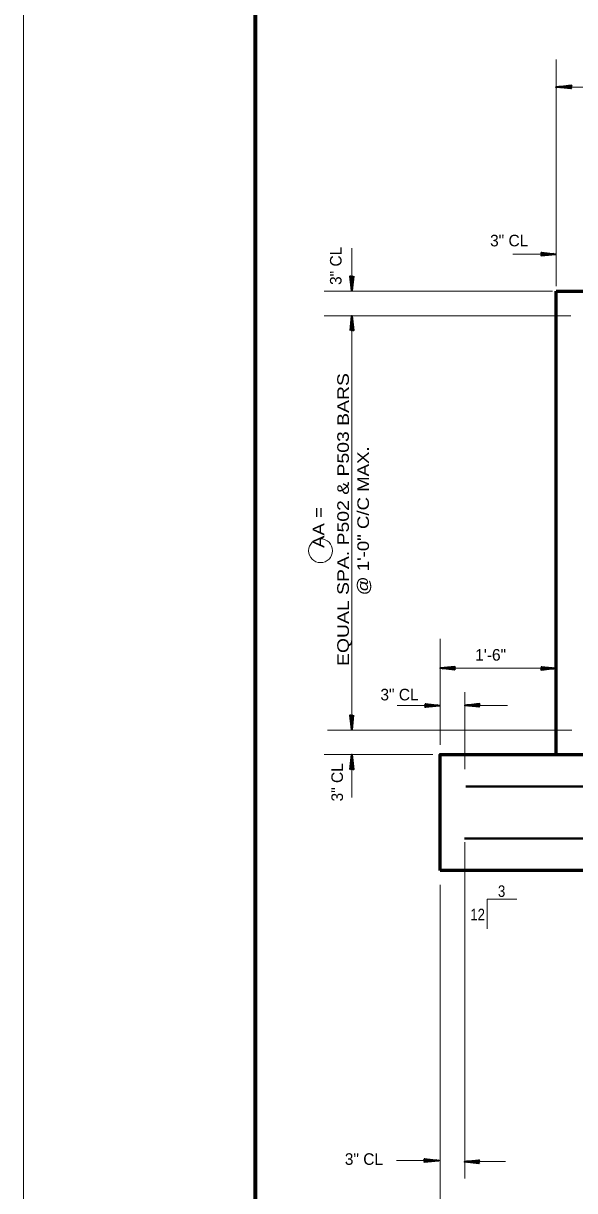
# Model space of a CAD drawing. Extents: x 6.34 to 9.53, y -1.46 to 0.53.
# Drawn here: x 6.336 to 6.732, y -1.036 to -0.197 of the extents above; entities that cross this region are included whole.
import ezdxf
from ezdxf.enums import TextEntityAlignment as Align

# ---------------------------------------------------------------- set-up
doc = ezdxf.new("R2010")
doc.units = 0
doc.header["$LTSCALE"] = 0.0033
doc.layers.add('1', color=7, linetype='Continuous', lineweight=40)

msp = doc.modelspace()

# ---------------------------------------------------------------- linework, layer by layer
at = {"layer": '1', "lineweight": 13}
for p, q in [((6.336, -1.46), (6.336, 0.52825)), ((6.718917, -0.386083), (6.718917, -0.222917)), ((6.572167, -0.3795), (6.572167, -0.358667)), ((6.687917, -0.362917), (6.70875, -0.362917)), ((6.716333, -0.389583), (6.55225, -0.389583)), ((6.729583, -0.40725), (6.552333, -0.40725)), ((6.572083, -0.704833), (6.572083, -0.408083)), ((6.635583, -0.715917), (6.635583, -0.639583)), ((6.6355, -0.660833), (6.718417, -0.660833)), ((6.65325, -0.733333), (6.65325, -0.678083)), ((6.60475, -0.6875), (6.625583, -0.6875)), ((6.66325, -0.6875), (6.684083, -0.6875)), ((6.730333, -0.70525), (6.55475, -0.70525)), ((6.630333, -0.722917), (6.55225, -0.722917)), ((6.572083, -0.753667), (6.572083, -0.732833)), ((6.65325, -0.78575), (6.65325, -1.027667)), ((6.635583, -0.8165), (6.635583, -1.076917)), ((6.669417, -0.826917), (6.69075, -0.826917)), ((6.669417, -0.826917), (6.669417, -0.84825)), ((6.60425, -1.014833), (6.625083, -1.014833)), ((6.66175, -1.015583), (6.682583, -1.015583))]:
    msp.add_line(p, q, dxfattribs=at)
at = {"layer": '1', "lineweight": 35}
for p, q in [((6.73, -0.242917), (6.719417, -0.242917)), ((6.72975, -0.24375), (6.721917, -0.24275)), ((6.72975, -0.24375), (6.721917, -0.242917)), ((6.72975, -0.243917), (6.721917, -0.243)), ((6.72975, -0.243917), (6.721917, -0.243)), ((6.72975, -0.243833), (6.721917, -0.243)), ((6.72975, -0.241833), (6.722417, -0.242667)), ((6.72975, -0.242), (6.722417, -0.24275)), ((6.72975, -0.242083), (6.722417, -0.242917)), ((6.729833, -0.24225), (6.7225, -0.243)), ((6.70825, -0.362917), (6.718833, -0.362917)), ((6.708417, -0.363583), (6.71575, -0.362833)), ((6.7085, -0.361917), (6.716333, -0.362833)), ((6.7085, -0.361917), (6.716333, -0.362833)), ((6.7085, -0.362), (6.716333, -0.362833)), ((6.7085, -0.362083), (6.716333, -0.362917)), ((6.7085, -0.362083), (6.716333, -0.363083)), ((6.7085, -0.36375), (6.715833, -0.362917)), ((6.7085, -0.363833), (6.715833, -0.363083)), ((6.7085, -0.364), (6.715833, -0.363167)), ((6.571083, -0.379167), (6.571917, -0.3865)), ((6.57125, -0.379167), (6.572, -0.3865)), ((6.571333, -0.379167), (6.572167, -0.3865)), ((6.5715, -0.379083), (6.57225, -0.386417)), ((6.573, -0.379167), (6.572, -0.387)), ((6.572167, -0.378917), (6.572167, -0.3895)), ((6.573, -0.379167), (6.572167, -0.387)), ((6.573167, -0.379167), (6.57225, -0.387)), ((6.573167, -0.379167), (6.57225, -0.387)), ((6.573083, -0.379167), (6.57225, -0.387)), ((6.571167, -0.417583), (6.572083, -0.40975)), ((6.571167, -0.417583), (6.572083, -0.40975)), ((6.57125, -0.417583), (6.572083, -0.40975)), ((6.571333, -0.417583), (6.572167, -0.40975)), ((6.571333, -0.417583), (6.572333, -0.40975)), ((6.572833, -0.417667), (6.572083, -0.410333)), ((6.572167, -0.417833), (6.572167, -0.40725)), ((6.573, -0.417583), (6.572167, -0.41025)), ((6.573083, -0.417583), (6.572333, -0.41025)), ((6.57325, -0.417583), (6.572417, -0.41025)), ((6.646167, -0.660833), (6.635583, -0.660833)), ((6.645917, -0.661667), (6.638083, -0.660667)), ((6.645917, -0.661667), (6.638083, -0.660833)), ((6.645917, -0.661833), (6.638083, -0.660917)), ((6.645917, -0.661833), (6.638083, -0.660917)), ((6.645917, -0.66175), (6.638083, -0.660917)), ((6.645917, -0.65975), (6.638583, -0.660583)), ((6.645917, -0.659917), (6.638583, -0.660667)), ((6.645917, -0.66), (6.638583, -0.660833)), ((6.646, -0.660167), (6.638667, -0.660917)), ((6.70825, -0.660833), (6.718833, -0.660833)), ((6.708417, -0.6615), (6.71575, -0.66075)), ((6.7085, -0.659833), (6.716333, -0.66075)), ((6.7085, -0.659833), (6.716333, -0.66075)), ((6.7085, -0.659917), (6.716333, -0.66075)), ((6.7085, -0.66), (6.716333, -0.660833)), ((6.7085, -0.66), (6.716333, -0.661)), ((6.7085, -0.661667), (6.715833, -0.660833)), ((6.7085, -0.66175), (6.715833, -0.661)), ((6.7085, -0.661917), (6.715833, -0.661083)), ((6.624917, -0.6875), (6.6355, -0.6875)), ((6.625083, -0.688167), (6.632417, -0.687417)), ((6.625167, -0.6865), (6.633, -0.687417)), ((6.625167, -0.6865), (6.633, -0.687417)), ((6.625167, -0.686583), (6.633, -0.687417)), ((6.625167, -0.686667), (6.633, -0.6875)), ((6.625167, -0.686667), (6.633, -0.687667)), ((6.625167, -0.688333), (6.6325, -0.6875)), ((6.625167, -0.688417), (6.6325, -0.687667)), ((6.625167, -0.688583), (6.6325, -0.68775)), ((6.663833, -0.6875), (6.65325, -0.6875)), ((6.663583, -0.688333), (6.65575, -0.687333)), ((6.663583, -0.688333), (6.65575, -0.6875)), ((6.663583, -0.6885), (6.65575, -0.687583)), ((6.663583, -0.6885), (6.65575, -0.687583)), ((6.663583, -0.688417), (6.65575, -0.687583)), ((6.663583, -0.686417), (6.65625, -0.68725)), ((6.663583, -0.686583), (6.65625, -0.687333)), ((6.663583, -0.686667), (6.65625, -0.6875)), ((6.663667, -0.686833), (6.656333, -0.687583)), ((6.571, -0.694833), (6.571833, -0.702167)), ((6.571167, -0.694833), (6.571917, -0.702167)), ((6.57125, -0.694833), (6.572083, -0.702167)), ((6.571417, -0.69475), (6.572167, -0.702083)), ((6.572917, -0.694833), (6.571917, -0.702667)), ((6.572083, -0.694583), (6.572083, -0.705167)), ((6.572917, -0.694833), (6.572083, -0.702667)), ((6.573083, -0.694833), (6.572167, -0.702667)), ((6.573083, -0.694833), (6.572167, -0.702667)), ((6.573, -0.694833), (6.572167, -0.702667)), ((6.571083, -0.73325), (6.572, -0.725417)), ((6.571083, -0.73325), (6.572, -0.725417)), ((6.571167, -0.73325), (6.572, -0.725417)), ((6.57125, -0.73325), (6.572083, -0.725417)), ((6.57125, -0.73325), (6.57225, -0.725417)), ((6.57275, -0.733333), (6.572, -0.726)), ((6.572083, -0.7335), (6.572083, -0.722917)), ((6.572917, -0.73325), (6.572083, -0.725917)), ((6.573, -0.73325), (6.57225, -0.725917)), ((6.573167, -0.73325), (6.572333, -0.725917)), ((6.624167, -1.014667), (6.63475, -1.014667)), ((6.624333, -1.015333), (6.631667, -1.014583)), ((6.624417, -1.013667), (6.63225, -1.014583)), ((6.624417, -1.013667), (6.63225, -1.014583)), ((6.624417, -1.01375), (6.63225, -1.014583)), ((6.624417, -1.013833), (6.63225, -1.014667)), ((6.624417, -1.013833), (6.63225, -1.014833)), ((6.624417, -1.0155), (6.63175, -1.014667)), ((6.624417, -1.015583), (6.63175, -1.014833)), ((6.624417, -1.01575), (6.63175, -1.014917)), ((6.663333, -1.016583), (6.6555, -1.015583)), ((6.663333, -1.014667), (6.656, -1.0155)), ((6.663333, -1.014833), (6.656, -1.015583)), ((6.663333, -1.014917), (6.656, -1.01575)), ((6.663417, -1.015083), (6.656083, -1.015833)), ((6.663583, -1.01575), (6.653, -1.01575)), ((6.663333, -1.016583), (6.6555, -1.01575)), ((6.663333, -1.01675), (6.6555, -1.015833)), ((6.663333, -1.01675), (6.6555, -1.015833)), ((6.663333, -1.016667), (6.6555, -1.015833))]:
    msp.add_line(p, q, dxfattribs=at)
at = {"layer": '1', "lineweight": 60}
for p, q in [((6.718917, -0.389583), (6.996917, -0.389583)), ((7.385583, -0.80625), (6.635583, -0.80625))]:
    msp.add_line(p, q, dxfattribs=at)
at = {"layer": '1', "lineweight": 70}
msp.add_lwpolyline([(9.449417, -1.3755), (9.449417, 0.444583), (6.50275, 0.444583), (6.50275, -1.3755)], dxfattribs=at)
at = {"layer": '1', "lineweight": 13}
msp.add_lwpolyline([(6.71825, -0.242917), (7.021083, -0.242917), (7.301583, -0.242917)], dxfattribs=at)
at = {"layer": '1', "lineweight": 35}
for points in [[(6.73, -0.244), (6.719417, -0.242917), (6.73, -0.24175), (6.729417, -0.242917)], [(6.72925, -0.243), (6.724583, -0.243083), (6.724583, -0.243), (6.7255, -0.243), (6.72925, -0.243083), (6.72625, -0.243167), (6.729417, -0.24325), (6.727167, -0.243333), (6.729417, -0.243417), (6.725917, -0.243167), (6.72125, -0.243), (6.722167, -0.24275), (6.720917, -0.24275), (6.72925, -0.24275), (6.726833, -0.242583), (6.729417, -0.242583), (6.724083, -0.243), (6.729417, -0.242333)], [(6.70825, -0.361833), (6.718833, -0.362917), (6.70825, -0.364083), (6.708833, -0.362917)], [(6.709, -0.362833), (6.713667, -0.36275), (6.713667, -0.362833), (6.71275, -0.362833), (6.709, -0.36275), (6.712, -0.362667), (6.708833, -0.362583), (6.711083, -0.3625), (6.708833, -0.362417), (6.712333, -0.362667), (6.717, -0.362833), (6.716083, -0.363083), (6.717333, -0.363083), (6.709, -0.363083), (6.711417, -0.36325), (6.708833, -0.36325), (6.714167, -0.362833), (6.708833, -0.3635)], [(6.57325, -0.378917), (6.572167, -0.3895), (6.571, -0.378917), (6.572167, -0.3795)], [(6.57225, -0.379667), (6.572333, -0.384333), (6.57225, -0.384333), (6.57225, -0.383417), (6.572333, -0.379667), (6.572417, -0.382667), (6.5725, -0.3795), (6.572583, -0.38175), (6.572667, -0.3795), (6.572417, -0.383), (6.57225, -0.387667), (6.572, -0.38675), (6.572, -0.388), (6.572, -0.379667), (6.571833, -0.382083), (6.571833, -0.3795), (6.57225, -0.384833), (6.571583, -0.3795)], [(6.571083, -0.417833), (6.572167, -0.40725), (6.573333, -0.417833), (6.572167, -0.41725)], [(6.572083, -0.417083), (6.572, -0.412417), (6.572083, -0.412417), (6.572083, -0.413333), (6.572, -0.417083), (6.571917, -0.414083), (6.571833, -0.41725), (6.57175, -0.415), (6.571667, -0.41725), (6.571917, -0.41375), (6.572083, -0.409083), (6.572333, -0.41), (6.572333, -0.40875), (6.572333, -0.417083), (6.5725, -0.414667), (6.5725, -0.41725), (6.572083, -0.411917), (6.57275, -0.41725)], [(6.646167, -0.661917), (6.635583, -0.660833), (6.646167, -0.659667), (6.645583, -0.660833)], [(6.645417, -0.660917), (6.64075, -0.661), (6.64075, -0.660917), (6.641667, -0.660917), (6.645417, -0.661), (6.642417, -0.661083), (6.645583, -0.661167), (6.643333, -0.66125), (6.645583, -0.661333), (6.642083, -0.661083), (6.637417, -0.660917), (6.638333, -0.660667), (6.637083, -0.660667), (6.645417, -0.660667), (6.643, -0.6605), (6.645583, -0.6605), (6.64025, -0.660917), (6.645583, -0.66025)], [(6.70825, -0.65975), (6.718833, -0.660833), (6.70825, -0.662), (6.708833, -0.660833)], [(6.709, -0.66075), (6.713667, -0.660667), (6.713667, -0.66075), (6.71275, -0.66075), (6.709, -0.660667), (6.712, -0.660583), (6.708833, -0.6605), (6.711083, -0.660417), (6.708833, -0.660333), (6.712333, -0.660583), (6.717, -0.66075), (6.716083, -0.661), (6.717333, -0.661), (6.709, -0.661), (6.711417, -0.661167), (6.708833, -0.661167), (6.714167, -0.66075), (6.708833, -0.661417)], [(6.624917, -0.686417), (6.6355, -0.6875), (6.624917, -0.688667), (6.6255, -0.6875)], [(6.625667, -0.687417), (6.630333, -0.687333), (6.630333, -0.687417), (6.629417, -0.687417), (6.625667, -0.687333), (6.628667, -0.68725), (6.6255, -0.687167), (6.62775, -0.687083), (6.6255, -0.687), (6.629, -0.68725), (6.633667, -0.687417), (6.63275, -0.687667), (6.634, -0.687667), (6.625667, -0.687667), (6.628083, -0.687833), (6.6255, -0.687833), (6.630833, -0.687417), (6.6255, -0.688083)], [(6.663833, -0.688583), (6.65325, -0.6875), (6.663833, -0.686333), (6.66325, -0.6875)], [(6.663083, -0.687583), (6.658417, -0.687667), (6.658417, -0.687583), (6.659333, -0.687583), (6.663083, -0.687667), (6.660083, -0.68775), (6.66325, -0.687833), (6.661, -0.687917), (6.66325, -0.688), (6.65975, -0.68775), (6.655083, -0.687583), (6.656, -0.687333), (6.65475, -0.687333), (6.663083, -0.687333), (6.660667, -0.687167), (6.66325, -0.687167), (6.657917, -0.687583), (6.66325, -0.686917)], [(6.573167, -0.694583), (6.572083, -0.705167), (6.570917, -0.694583), (6.572083, -0.695167)], [(6.572167, -0.695333), (6.57225, -0.7), (6.572167, -0.7), (6.572167, -0.699083), (6.57225, -0.695333), (6.572333, -0.698333), (6.572417, -0.695167), (6.5725, -0.697417), (6.572583, -0.695167), (6.572333, -0.698667), (6.572167, -0.703333), (6.571917, -0.702417), (6.571917, -0.703667), (6.571917, -0.695333), (6.57175, -0.69775), (6.57175, -0.695167), (6.572167, -0.7005), (6.5715, -0.695167)], [(6.571, -0.7335), (6.572083, -0.722917), (6.57325, -0.7335), (6.572083, -0.732917)], [(6.572, -0.73275), (6.571917, -0.728083), (6.572, -0.728083), (6.572, -0.729), (6.571917, -0.73275), (6.571833, -0.72975), (6.57175, -0.732917), (6.571667, -0.730667), (6.571583, -0.732917), (6.571833, -0.729417), (6.572, -0.72475), (6.57225, -0.725667), (6.57225, -0.724417), (6.57225, -0.73275), (6.572417, -0.730333), (6.572417, -0.732917), (6.572, -0.727583), (6.572667, -0.732917)], [(6.624167, -1.013583), (6.63475, -1.014667), (6.624167, -1.015833), (6.62475, -1.014667)], [(6.624917, -1.014583), (6.629583, -1.0145), (6.629583, -1.014583), (6.628667, -1.014583), (6.624917, -1.0145), (6.627917, -1.014417), (6.62475, -1.014333), (6.627, -1.01425), (6.62475, -1.014167), (6.62825, -1.014417), (6.632917, -1.014583), (6.632, -1.014833), (6.63325, -1.014833), (6.624917, -1.014833), (6.627333, -1.015), (6.62475, -1.015), (6.630083, -1.014583), (6.62475, -1.01525)], [(6.663583, -1.016833), (6.653, -1.01575), (6.663583, -1.014583), (6.663, -1.01575)], [(6.662833, -1.015833), (6.658167, -1.015917), (6.658167, -1.015833), (6.659083, -1.015833), (6.662833, -1.015917), (6.659833, -1.016), (6.663, -1.016083), (6.66075, -1.016167), (6.663, -1.01625), (6.6595, -1.016), (6.654833, -1.015833), (6.65575, -1.015583), (6.6545, -1.015583), (6.662833, -1.015583), (6.660417, -1.015417), (6.663, -1.015417), (6.657667, -1.015833), (6.663, -1.015167)]]:
    msp.add_lwpolyline(points, close=True, dxfattribs=at)
for points in [[(6.72925, -0.243), (6.729667, -0.24375), (6.729417, -0.2435), (6.72925, -0.243167), (6.729, -0.24325), (6.729167, -0.243583), (6.729333, -0.242833), (6.7295, -0.242333), (6.72975, -0.241917)], [(6.709, -0.362833), (6.708583, -0.362083), (6.708833, -0.362333), (6.709, -0.362667), (6.70925, -0.362583), (6.709083, -0.36225), (6.708917, -0.363), (6.70875, -0.3635), (6.7085, -0.363917)], [(6.57225, -0.379667), (6.573, -0.37925), (6.57275, -0.3795), (6.572417, -0.379667), (6.5725, -0.379917), (6.572833, -0.37975), (6.572083, -0.379583), (6.571583, -0.379417), (6.571167, -0.379167)], [(6.572083, -0.417083), (6.571333, -0.4175), (6.571583, -0.41725), (6.571917, -0.417083), (6.571833, -0.416833), (6.5715, -0.417), (6.57225, -0.417167), (6.57275, -0.417333), (6.573167, -0.417583)], [(6.645417, -0.660917), (6.645833, -0.661667), (6.645583, -0.661417), (6.645417, -0.661083), (6.645167, -0.661167), (6.645333, -0.6615), (6.6455, -0.66075), (6.645667, -0.66025), (6.645917, -0.659833)], [(6.709, -0.66075), (6.708583, -0.66), (6.708833, -0.66025), (6.709, -0.660583), (6.70925, -0.6605), (6.709083, -0.660167), (6.708917, -0.660917), (6.70875, -0.661417), (6.7085, -0.661833)], [(6.625667, -0.687417), (6.62525, -0.686667), (6.6255, -0.686917), (6.625667, -0.68725), (6.625917, -0.687167), (6.62575, -0.686833), (6.625583, -0.687583), (6.625417, -0.688083), (6.625167, -0.6885)], [(6.663083, -0.687583), (6.6635, -0.688333), (6.66325, -0.688083), (6.663083, -0.68775), (6.662833, -0.687833), (6.663, -0.688167), (6.663167, -0.687417), (6.663333, -0.686917), (6.663583, -0.6865)], [(6.572167, -0.695333), (6.572917, -0.694917), (6.572667, -0.695167), (6.572333, -0.695333), (6.572417, -0.695583), (6.57275, -0.695417), (6.572, -0.69525), (6.5715, -0.695083), (6.571083, -0.694833)], [(6.572, -0.73275), (6.57125, -0.733167), (6.5715, -0.732917), (6.571833, -0.73275), (6.57175, -0.7325), (6.571417, -0.732667), (6.572167, -0.732833), (6.572667, -0.733), (6.573083, -0.73325)], [(6.624917, -1.014583), (6.6245, -1.013833), (6.62475, -1.014083), (6.624917, -1.014417), (6.625167, -1.014333), (6.625, -1.014), (6.624833, -1.01475), (6.624667, -1.01525), (6.624417, -1.015667)], [(6.662833, -1.015833), (6.66325, -1.016583), (6.663, -1.016333), (6.662833, -1.016), (6.662583, -1.016083), (6.66275, -1.016417), (6.662917, -1.015667), (6.663083, -1.015167), (6.663333, -1.01475)]]:
    msp.add_lwpolyline(points, dxfattribs=at)
at = {"layer": '1', "lineweight": 60}
for points in [[(6.635583, -0.80625), (6.635583, -0.722917), (6.718917, -0.722917), (6.718917, -0.389583)], [(6.718917, -0.722917), (6.962083, -0.722917), (7.30225, -0.722917)]]:
    msp.add_lwpolyline(points, dxfattribs=at)
at = {"layer": '1'}
for points in [[(6.654, -0.745833), (6.962083, -0.745833), (7.023833, -0.745833)], [(6.653167, -0.78325), (6.962167, -0.78325), (7.024083, -0.78325)]]:
    msp.add_lwpolyline(points, dxfattribs=at)
at = {"layer": '1', "lineweight": 13}
msp.add_circle((6.549667, -0.57625), 0.008584, dxfattribs=at)

# ---------------------------------------------------------------- texts
at = {"layer": '1'}
for s, p in [('3" CL', (6.6715, -0.357417)), ('1\'-6"', (6.660833, -0.655333)), ('3" CL', (6.592667, -0.683917)), ('3" CL', (6.567083, -1.017917))]:
    msp.add_text(s, height=0.008334, dxfattribs=at).set_placement(p)
for p in [(6.56475, -0.385167), (6.56575, -0.756583)]:
    msp.add_text('3" CL', height=0.008334, rotation=90, dxfattribs=at).set_placement(p)
for s, width, p in [('EQUAL SPA. P502 & P503 BARS', 1.25, (6.57, -0.659167)), ('@ 1\'-0" C/C MAX.', 1.2, (6.584417, -0.608333))]:
    msp.add_text(s, height=0.008334, rotation=90, dxfattribs=dict(at, width=width)).set_placement(p)
at = {"layer": '1', "width": 1.2}
msp.add_text('AA =      ', height=0.008334, rotation=90, dxfattribs=at).set_placement((6.552417, -0.548458), align=Align.CENTER)
at = {"layer": '1', "width": 0.85}
msp.add_text('3', height=0.008334, dxfattribs=at).set_placement((6.679792, -0.82525), align=Align.CENTER)
msp.add_text('12', height=0.008334, dxfattribs=at).set_placement((6.667833, -0.842083), align=Align.RIGHT)

doc.saveas('drawing.dxf')
